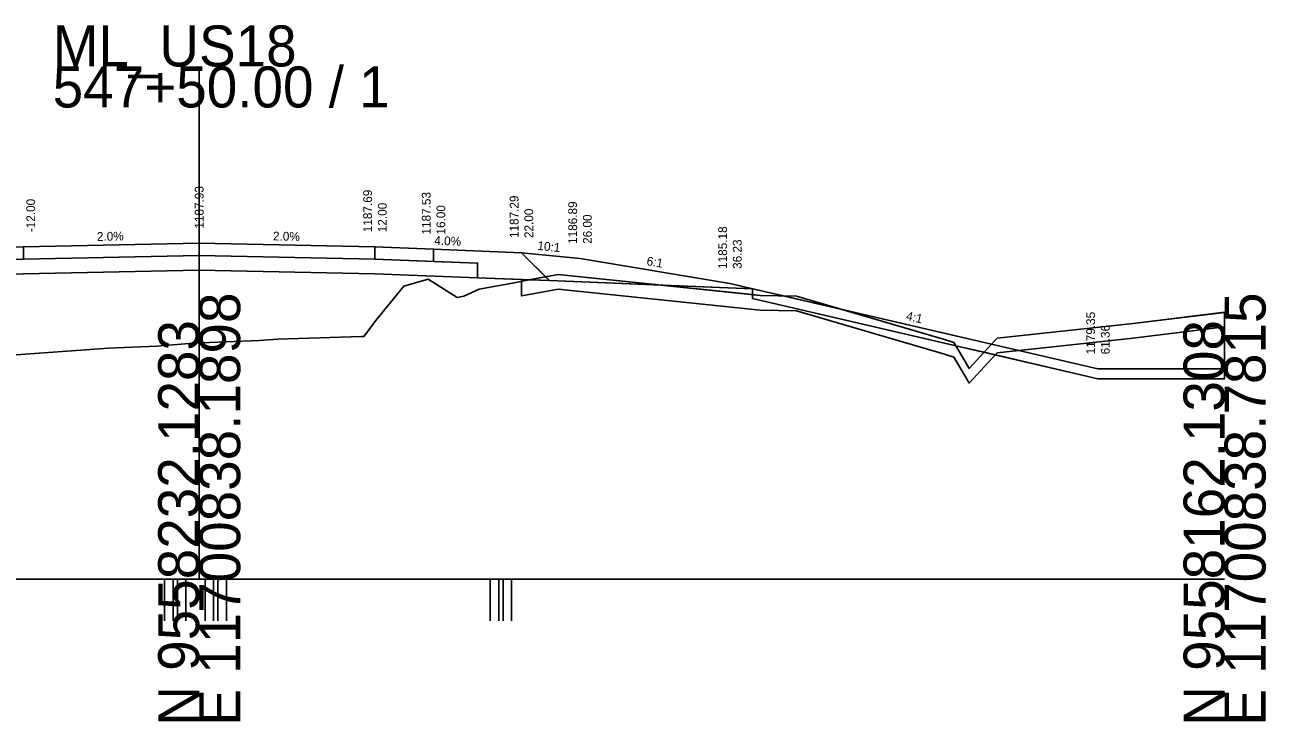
# Model space of a CAD drawing. Extents: x -75 to 1143, y -10 to 8583.
# Drawn here: x 58.1 to 142.8, y 4490.3 to 4537.8 of the extents above; entities that cross this region are included whole.
import ezdxf

# ---------------------------------------------------------------- set-up
doc = ezdxf.new("R2010")
doc.units = 0
for name, color, linetype in [('brgPreStructureNew', 7, 'Continuous'), ('Default', 7, 'Continuous'), ('Draft_XS_Text', 7, 'Continuous'), ('dsnGeopakCellCrossSection', 7, 'Continuous'), ('dsnXSEarthwork', 7, 'Continuous'), ('dsnXsEarthworkShapesCF', 7, 'Continuous'), ('dsnXsEarthworkShapesTPS', 7, 'Continuous'), ('dsnXsEarthworkShapesUCSG', 7, 'Continuous'), ('dsnXsEarthworkShapesUCTP', 7, 'Continuous'), ('dsnXsExistingGround', 7, 'Continuous'), ('dsnXsExTsStripping', 7, 'Continuous'), ('dsnXsPCCPavement', 7, 'Continuous'), ('dsnXsShldrEarthFill', 7, 'Continuous'), ('dsnXsShldrGranular', 7, 'Continuous'), ('dsnXsShldrPCC', 7, 'Continuous'), ('dsnXsSideSlopes', 7, 'Continuous'), ('dsnXsSideSlopesDressing', 7, 'Continuous'), ('dsnXsSubbase', 7, 'Continuous'), ('dsnXsTextOffsetElevFinGrd', 7, 'Continuous'), ('dsnXsTextPavementSlope', 7, 'Continuous'), ('NONPLOT1', 7, 'Continuous')]:
    doc.layers.add(name, color=color, linetype=linetype)

msp = doc.modelspace()

# ---------------------------------------------------------------- linework, layer by layer
at = {"layer": 'brgPreStructureNew'}
for p, q in [((69.093, 4500), (69.093, 4497.146)), ((70.401, 4500), (70.401, 4497.146)), ((91.322, 4500), (91.322, 4497.146))]:
    msp.add_line(p, q, dxfattribs=at)
at = {"layer": 'dsnGeopakCellCrossSection'}
for p, q in [((70, 4500), (70, 4535)), ((0, 4500), (70, 4500)), ((70, 4500), (140, 4500))]:
    msp.add_line(p, q, dxfattribs=at)
at = {"layer": 'dsnXSEarthwork'}
msp.add_lwpolyline([(48, 4522.288), (54, 4522.528), (58, 4522.688), (70, 4522.928), (82, 4522.688), (86, 4522.528), (92, 4522.288)], dxfattribs=at)
at = {"layer": 'dsnXsEarthworkShapesCF'}
for points in [[(58, 4522.688), (70, 4522.928), (82, 4522.688), (86, 4522.528), (92, 4522.288), (96, 4521.888), (106.234, 4520.182), (107.776, 4519.824), (109.89, 4519.333), (110.781, 4519.31), (113.811, 4518.423), (124.091, 4516.036), (124.469, 4516.441), (133.768, 4517.454), (140, 4518.216), (140, 4514.349), (139.999, 4513.682), (131.358, 4513.682), (123.584, 4515.487), (122.574, 4514.382), (122.281, 4514.856), (121.658, 4515.934), (107.776, 4519.157), (107.776, 4519.429), (101.587, 4520.072), (93.909, 4520.379), (92.526, 4520.434), (91.39, 4520.215), (89.109, 4519.795), (88.078, 4519.31), (87.603, 4519.235), (85.633, 4520.485), (83.966, 4519.997), (82.161, 4517.772), (81.248, 4516.565), (81.12, 4516.562), (81.091, 4516.56), (75.361, 4516.374), (74.086, 4516.283), (69.589, 4516.106), (67.102, 4515.913), (63.803, 4515.761), (56.868, 4515.27)], [(58, 4520.855), (70, 4521.095), (82, 4520.855), (89, 4520.575), (92.526, 4520.434), (91.39, 4520.215), (89.109, 4519.795), (88.078, 4519.31), (87.603, 4519.235), (85.633, 4520.485), (83.966, 4519.997), (82.161, 4517.772), (81.248, 4516.565), (81.12, 4516.562), (81.091, 4516.56), (75.361, 4516.374), (74.086, 4516.283), (69.589, 4516.106), (67.102, 4515.913), (63.803, 4515.761), (56.868, 4515.27)]]:
    msp.add_lwpolyline(points, dxfattribs=at)
for points in [[(58, 4522.688), (58, 4521.855), (70, 4522.095), (82, 4521.855), (82, 4522.688), (70, 4522.928)], [(70, 4521.095), (82, 4520.855), (89, 4520.575), (89, 4521.575), (86, 4521.695), (82, 4521.855), (70, 4522.095), (58, 4521.855), (54, 4521.695), (51, 4521.575), (51, 4520.575), (58, 4520.855)], [(82, 4521.855), (86, 4521.695), (86, 4522.528), (82, 4522.688)], [(93.644, 4520.644), (92, 4522.288), (86, 4522.528), (86, 4521.695), (89, 4521.575), (89, 4520.575), (92.526, 4520.434), (92.644, 4520.457)], [(93.644, 4520.644), (92, 4522.288), (96, 4521.888), (106.234, 4520.182), (107.776, 4519.824), (101.587, 4520.072), (94.511, 4520.806)], [(93.909, 4520.379), (93.644, 4520.644), (92.644, 4520.457), (92.526, 4520.434)], [(93.909, 4520.379), (93.644, 4520.644), (94.511, 4520.806), (101.587, 4520.072)], [(101.587, 4520.072), (107.776, 4519.429), (107.776, 4519.824)], [(109.89, 4519.333), (107.776, 4519.824), (107.776, 4519.429), (108.291, 4519.375)], [(107.776, 4519.429), (107.776, 4519.157), (121.658, 4515.934), (121.528, 4516.161), (120.888, 4516.351), (113.811, 4518.423), (109.89, 4519.333), (108.291, 4519.375)], [(109.89, 4519.333), (110.781, 4519.31), (113.811, 4518.423)], [(121.528, 4516.161), (121.658, 4515.934), (123.584, 4515.487), (123.868, 4515.797), (124.091, 4516.036), (113.811, 4518.423), (120.888, 4516.351)], [(140, 4518.216), (140, 4514.349), (131.358, 4514.349), (124.091, 4516.036), (124.469, 4516.441), (133.768, 4517.454)], [(122.281, 4514.856), (122.574, 4514.382), (123.584, 4515.487), (121.658, 4515.934)], [(140, 4514.349), (139.999, 4513.682), (131.358, 4513.682), (123.584, 4515.487), (123.868, 4515.797), (124.091, 4516.036), (131.358, 4514.349)]]:
    msp.add_lwpolyline(points, close=True, dxfattribs=at)
at = {"layer": 'dsnXsEarthworkShapesTPS'}
msp.add_lwpolyline([(92, 4520.333), (92, 4519.333), (92.644, 4519.457), (94.511, 4519.806), (108.291, 4518.375), (110.781, 4518.31), (120.888, 4515.351), (121.528, 4515.161), (122.281, 4513.856), (122.574, 4513.382), (123.868, 4514.797), (124.469, 4515.441), (133.768, 4516.454), (139.999, 4517.215), (139.999, 4518.215), (133.768, 4517.454), (124.469, 4516.441), (123.868, 4515.797), (122.574, 4514.382), (122.281, 4514.856), (121.528, 4516.161), (120.888, 4516.351), (110.781, 4519.31), (108.291, 4519.375), (94.511, 4520.806), (92.644, 4520.457)], close=True, dxfattribs=at)
at = {"layer": 'dsnXsEarthworkShapesUCSG'}
for points in [[(58, 4522.688), (70, 4522.928), (82, 4522.688), (86, 4522.528), (92, 4522.288), (96, 4521.888), (106.234, 4520.182), (107.776, 4519.824), (109.89, 4519.333), (110.781, 4519.31), (113.811, 4518.423), (124.091, 4516.036), (124.469, 4516.441), (133.768, 4517.454), (140, 4518.216), (140, 4514.349), (139.999, 4513.682), (131.358, 4513.682), (123.584, 4515.487), (122.574, 4514.382), (122.281, 4514.856), (121.658, 4515.934), (107.776, 4519.157), (107.776, 4519.429), (101.587, 4520.072), (93.909, 4520.379), (92.526, 4520.434), (91.39, 4520.215), (89.109, 4519.795), (88.078, 4519.31), (87.603, 4519.235), (85.633, 4520.485), (83.966, 4519.997), (82.161, 4517.772), (81.248, 4516.565), (81.12, 4516.562), (81.091, 4516.56), (75.361, 4516.374), (74.086, 4516.283), (69.589, 4516.106), (67.102, 4515.913), (63.803, 4515.761), (56.868, 4515.27)], [(56.868, 4515.27), (63.803, 4515.761), (67.102, 4515.913), (69.589, 4516.106), (74.086, 4516.283), (75.361, 4516.374), (81.091, 4516.56), (81.12, 4516.562), (81.248, 4516.565), (82.161, 4517.772), (83.966, 4519.997), (85.633, 4520.485), (87.603, 4519.235), (88.078, 4519.31), (89.109, 4519.795), (91.39, 4520.215), (92.526, 4520.434), (89, 4520.575), (82, 4520.855), (70, 4521.095), (58, 4520.855)]]:
    msp.add_lwpolyline(points, dxfattribs=at)
for points in [[(58, 4522.688), (58, 4521.855), (70, 4522.095), (82, 4521.855), (82, 4522.688), (70, 4522.928)], [(70, 4521.095), (82, 4520.855), (89, 4520.575), (89, 4521.575), (86, 4521.695), (82, 4521.855), (70, 4522.095), (58, 4521.855), (54, 4521.695), (51, 4521.575), (51, 4520.575), (58, 4520.855)], [(82, 4522.688), (86, 4522.528), (86, 4521.695), (82, 4521.855)], [(93.644, 4520.644), (92, 4522.288), (86, 4522.528), (86, 4521.695), (89, 4521.575), (89, 4520.575), (92.526, 4520.434), (92.644, 4520.457)], [(93.644, 4520.644), (92, 4522.288), (96, 4521.888), (106.234, 4520.182), (107.776, 4519.824), (101.587, 4520.072), (94.511, 4520.806)], [(93.909, 4520.379), (93.644, 4520.644), (92.644, 4520.457), (92.526, 4520.434)], [(93.909, 4520.379), (93.644, 4520.644), (94.511, 4520.806), (101.587, 4520.072)], [(101.587, 4520.072), (107.776, 4519.429), (107.776, 4519.824)], [(109.89, 4519.333), (107.776, 4519.824), (107.776, 4519.429), (108.291, 4519.375)], [(107.776, 4519.429), (107.776, 4519.157), (121.658, 4515.934), (121.528, 4516.161), (120.888, 4516.351), (113.811, 4518.423), (109.89, 4519.333), (108.291, 4519.375)], [(109.89, 4519.333), (110.781, 4519.31), (113.811, 4518.423)], [(121.528, 4516.161), (121.658, 4515.934), (123.584, 4515.487), (123.868, 4515.797), (124.091, 4516.036), (113.811, 4518.423), (120.888, 4516.351)], [(140, 4518.216), (140, 4514.349), (131.358, 4514.349), (124.091, 4516.036), (124.469, 4516.441), (133.768, 4517.454)], [(122.281, 4514.856), (122.574, 4514.382), (123.584, 4515.487), (121.658, 4515.934)], [(140, 4514.349), (139.999, 4513.682), (131.358, 4513.682), (123.584, 4515.487), (123.868, 4515.797), (124.091, 4516.036), (131.358, 4514.349)]]:
    msp.add_lwpolyline(points, close=True, dxfattribs=at)
at = {"layer": 'dsnXsEarthworkShapesUCTP'}
for points in [[(58, 4522.688), (70, 4522.928), (82, 4522.688), (86, 4522.528), (92, 4522.288), (96, 4521.888), (106.234, 4520.182), (107.776, 4519.824), (109.89, 4519.333), (110.781, 4519.31), (113.811, 4518.423), (124.091, 4516.036), (124.469, 4516.441), (133.768, 4517.454), (140, 4518.216), (140, 4514.349), (139.999, 4513.682), (131.358, 4513.682), (123.584, 4515.487), (122.574, 4514.382), (122.281, 4514.856), (121.658, 4515.934), (107.776, 4519.157), (107.776, 4519.429), (101.587, 4520.072), (93.909, 4520.379), (92.526, 4520.434), (91.39, 4520.215), (89.109, 4519.795), (88.078, 4519.31), (87.603, 4519.235), (85.633, 4520.485), (83.966, 4519.997), (82.161, 4517.772), (81.248, 4516.565), (81.12, 4516.562), (81.091, 4516.56), (75.361, 4516.374), (74.086, 4516.283), (69.589, 4516.106), (67.102, 4515.913), (63.803, 4515.761), (56.868, 4515.27)], [(58, 4520.855), (70, 4521.095), (82, 4520.855), (89, 4520.575), (92.526, 4520.434), (91.39, 4520.215), (89.109, 4519.795), (88.078, 4519.31), (87.603, 4519.235), (85.633, 4520.485), (83.966, 4519.997), (82.161, 4517.772), (81.248, 4516.565), (81.12, 4516.562), (81.091, 4516.56), (75.361, 4516.374), (74.086, 4516.283), (69.589, 4516.106), (67.102, 4515.913), (63.803, 4515.761), (56.868, 4515.27)]]:
    msp.add_lwpolyline(points, dxfattribs=at)
for points in [[(58, 4522.688), (58, 4521.855), (70, 4522.095), (82, 4521.855), (82, 4522.688), (70, 4522.928)], [(70, 4521.095), (82, 4520.855), (89, 4520.575), (89, 4521.575), (86, 4521.695), (82, 4521.855), (70, 4522.095), (58, 4521.855), (54, 4521.695), (51, 4521.575), (51, 4520.575), (58, 4520.855)], [(82, 4521.855), (86, 4521.695), (86, 4522.528), (82, 4522.688)], [(86, 4521.695), (89, 4521.575), (89, 4520.575), (92.526, 4520.434), (92.644, 4520.457), (93.644, 4520.644), (92, 4522.288), (86, 4522.528)], [(96, 4521.888), (92, 4522.288), (93.644, 4520.644), (94.511, 4520.806), (101.587, 4520.072), (107.776, 4519.824), (106.234, 4520.182)], [(93.909, 4520.379), (93.644, 4520.644), (92.644, 4520.457), (92.526, 4520.434)], [(93.909, 4520.379), (93.644, 4520.644), (94.511, 4520.806), (101.587, 4520.072)], [(101.587, 4520.072), (107.776, 4519.824), (107.776, 4519.429)], [(109.89, 4519.333), (107.776, 4519.824), (107.776, 4519.429), (108.291, 4519.375)], [(121.528, 4516.161), (121.658, 4515.934), (107.776, 4519.157), (107.776, 4519.429), (108.291, 4519.375), (109.89, 4519.333), (113.811, 4518.423), (120.888, 4516.351)], [(109.89, 4519.333), (110.781, 4519.31), (113.811, 4518.423)], [(121.528, 4516.161), (121.658, 4515.934), (123.584, 4515.487), (123.868, 4515.797), (124.091, 4516.036), (113.811, 4518.423), (120.888, 4516.351)], [(140, 4518.216), (140, 4514.349), (131.358, 4514.349), (124.091, 4516.036), (124.469, 4516.441), (133.768, 4517.454)], [(122.281, 4514.856), (122.574, 4514.382), (123.584, 4515.487), (121.658, 4515.934)], [(140, 4514.349), (139.999, 4513.682), (131.358, 4513.682), (123.584, 4515.487), (123.868, 4515.797), (124.091, 4516.036), (131.358, 4514.349)]]:
    msp.add_lwpolyline(points, close=True, dxfattribs=at)
at = {"layer": 'dsnXsExistingGround'}
msp.add_lwpolyline([(56.868, 4515.27), (63.803, 4515.761), (67.102, 4515.913), (69.589, 4516.106), (74.086, 4516.283), (75.361, 4516.374), (81.091, 4516.56), (81.12, 4516.562), (81.248, 4516.565), (82.161, 4517.772), (83.966, 4519.997), (85.633, 4520.485), (87.603, 4519.235), (88.078, 4519.31), (89.109, 4519.795), (91.39, 4520.215), (92.644, 4520.457), (94.511, 4520.806), (108.291, 4519.375), (110.781, 4519.31), (120.888, 4516.351), (121.528, 4516.161), (122.281, 4514.856), (122.574, 4514.382), (123.868, 4515.797), (124.469, 4516.441), (133.768, 4517.454), (140, 4518.216), (140, 4514.349)], dxfattribs=at)
at = {"layer": 'dsnXsExTsStripping'}
for p, q in [((92, 4520.333), (92, 4519.333)), ((139.999, 4518.215), (139.999, 4517.215))]:
    msp.add_line(p, q, dxfattribs=at)
for points in [[(92, 4520.333), (92.644, 4520.457), (94.511, 4520.806), (108.291, 4519.375), (110.781, 4519.31), (120.888, 4516.351), (121.528, 4516.161), (122.281, 4514.856), (122.574, 4514.382), (123.868, 4515.797), (124.469, 4516.441), (133.768, 4517.454), (139.999, 4518.215)], [(92, 4519.333), (92.644, 4519.457), (94.511, 4519.806), (108.291, 4518.375), (110.781, 4518.31), (120.888, 4515.351), (121.528, 4515.161), (122.281, 4513.856), (122.574, 4513.382), (123.868, 4514.797), (124.469, 4515.441), (133.768, 4516.454), (139.999, 4517.215)]]:
    msp.add_lwpolyline(points, dxfattribs=at)
at = {"layer": 'dsnXsPCCPavement'}
msp.add_lwpolyline([(70, 4522.928), (58, 4522.688), (58, 4522.688), (58, 4521.855), (70, 4522.095), (70, 4522.095), (70, 4522.095), (82, 4521.855), (82, 4522.688), (82, 4522.688), (70, 4522.928), (70, 4522.928), (70, 4522.928)], dxfattribs=at)
at = {"layer": 'dsnXsShldrEarthFill'}
msp.add_line((93.909, 4520.379), (107.776, 4519.824), dxfattribs=at)
at = {"layer": 'dsnXsShldrGranular'}
msp.add_lwpolyline([(86, 4522.528), (86, 4522.528), (86, 4522.528), (86, 4521.695), (86, 4521.695), (89, 4521.575), (89, 4521.575), (89, 4520.575), (89, 4520.575), (93.909, 4520.379), (92, 4522.288), (92, 4522.288), (86, 4522.528)], dxfattribs=at)
at = {"layer": 'dsnXsShldrPCC'}
msp.add_lwpolyline([(82, 4522.688), (82, 4521.855), (86, 4521.695), (86, 4522.528), (82, 4522.688)], dxfattribs=at)
at = {"layer": 'dsnXsSideSlopes'}
msp.add_lwpolyline([(140, 4514.349), (131.358, 4514.349), (131.358, 4514.349), (106.234, 4520.182), (106.234, 4520.182), (96, 4521.888), (92, 4522.288), (92, 4522.288)], dxfattribs=at)
at = {"layer": 'dsnXsSideSlopesDressing'}
for p, q in [((107.776, 4519.824), (107.776, 4519.157)), ((139.999, 4514.349), (139.999, 4513.682))]:
    msp.add_line(p, q, dxfattribs=at)
msp.add_lwpolyline([(139.999, 4513.682), (131.358, 4513.682), (131.358, 4513.682), (107.776, 4519.157)], dxfattribs=at)
at = {"layer": 'dsnXsSubbase'}
msp.add_lwpolyline([(51, 4521.575), (51, 4520.575), (58, 4520.855), (58, 4520.855), (70, 4521.095), (70, 4521.095), (70, 4521.095), (82, 4520.855), (82, 4520.855), (89, 4520.575), (89, 4521.575), (89, 4521.575), (82, 4521.855), (82, 4521.855), (70, 4522.095), (70, 4522.095), (70, 4522.095), (58, 4521.855), (58, 4521.855), (51, 4521.575), (51, 4521.575)], dxfattribs=at)
at = {"layer": 'NONPLOT1'}
for p, q in [((67.641, 4500), (67.641, 4497.146)), ((68.222, 4500), (68.222, 4497.146)), ((68.512, 4500), (68.512, 4497.146)), ((70.982, 4500), (70.982, 4497.146)), ((71.273, 4500), (71.273, 4497.146)), ((71.854, 4500), (71.854, 4497.146)), ((89.87, 4500), (89.87, 4497.146)), ((90.451, 4500), (90.451, 4497.146)), ((90.741, 4500), (90.741, 4497.146))]:
    msp.add_line(p, q, dxfattribs=at)

# ---------------------------------------------------------------- texts
at = {"layer": 'Default'}
for p in [(69.996, 4522.924), (81.996, 4522.684), (85.996, 4522.524), (91.996, 4522.284), (95.996, 4521.884), (69.996, 4521.091), (81.996, 4520.851), (106.23, 4520.178), (131.354, 4514.345), (131.354, 4514.345)]:
    msp.add_text('X', height=0.00781, dxfattribs=at).set_placement(p)
at = {"layer": 'Draft_XS_Text'}
msp.add_text('Sta. 547+50.00 R1', height=0.02, dxfattribs=at).set_placement((69.856, 4499.84))
at = {"layer": 'dsnGeopakCellCrossSection'}
for s, p in [('ML_US18', (60, 4535)), ('547+50.00 / 1', (60, 4532.2))]:
    msp.add_text(s, height=2.8, dxfattribs=at).set_placement(p)
for s, p in [('E 11700838.1898', (72.8, 4490)), ('E 11700838.7815', (142.8, 4490)), ('N 9558232.1283', (70, 4490)), ('N 9558162.1308', (140, 4490))]:
    msp.add_text(s, height=2.8, rotation=90, dxfattribs=at).set_placement(p)
at = {"layer": 'dsnXsTextOffsetElevFinGrd'}
for s, p in [('1187.93', (70.3, 4523.928)), ('1187.69', (81.8, 4523.688)), ('1187.53', (85.8, 4523.528)), ('1187.53', (85.8, 4523.528)), ('1187.29', (91.8, 4523.288)), ('-12.00', (58.8, 4523.688)), ('12.00', (82.8, 4523.688)), ('16.00', (86.8, 4523.528)), ('16.00', (86.8, 4523.528)), ('22.00', (92.8, 4523.288)), ('1186.89', (95.8, 4522.888)), ('26.00', (96.8, 4522.888)), ('1185.18', (106.034, 4521.182)), ('1185.18', (106.034, 4521.182)), ('36.23', (107.034, 4521.182)), ('36.23', (107.034, 4521.182)), ('1179.35', (131.158, 4515.349)), ('61.36', (132.158, 4515.349))]:
    msp.add_text(s, height=0.6, rotation=90, dxfattribs=at).set_placement(p)
at = {"layer": 'dsnXsTextPavementSlope'}
for s, rotation, p in [('2.0%', 1.14576, (63.023, 4523.089)), ('2.0%', 358.85424, (75.035, 4523.127)), ('4.0%', 357.70939, (86.042, 4522.827)), ('10:1', 354.28941, (93.071, 4522.483)), ('6:1', 350.53582, (100.509, 4521.441)), ('4:1', 346.92891, (118.215, 4517.708))]:
    msp.add_text(s, height=0.6, rotation=rotation, dxfattribs=at).set_placement(p)

doc.saveas('drawing.dxf')
